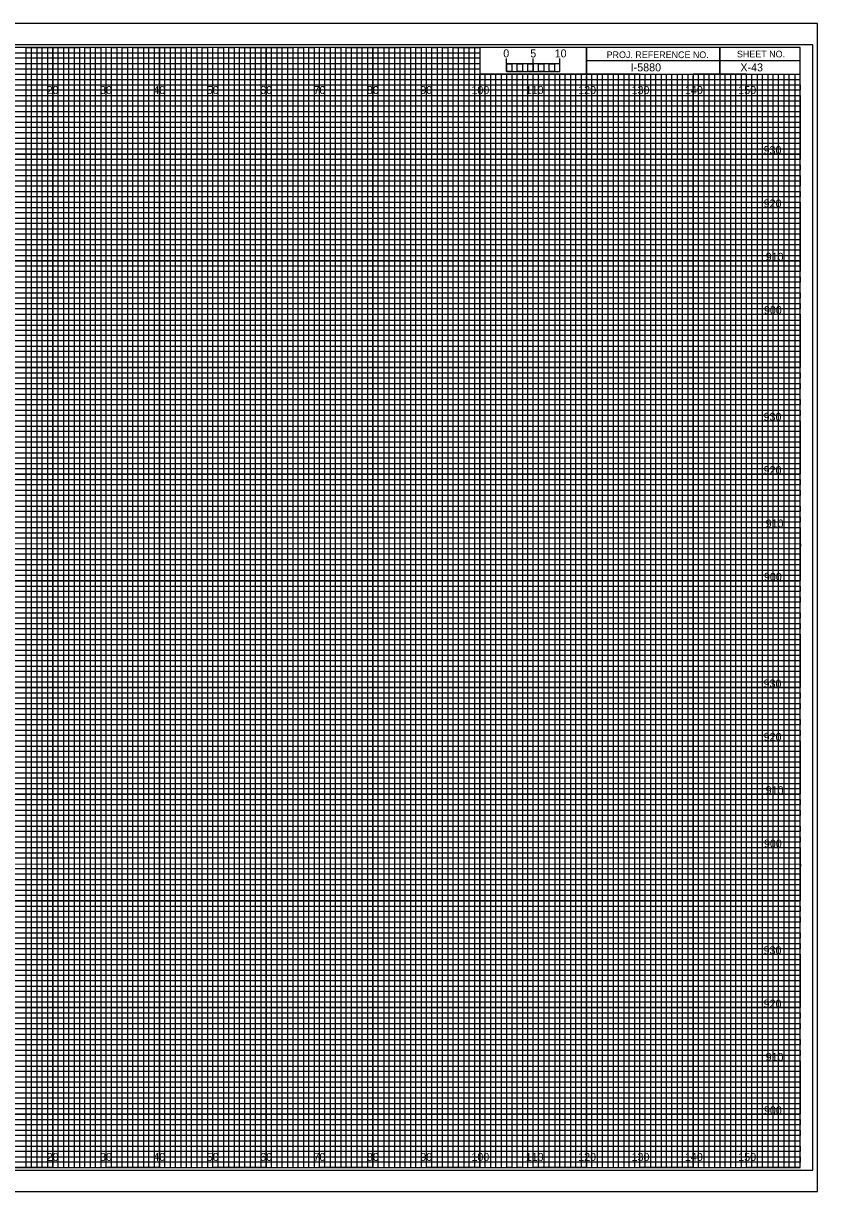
# Model space of a CAD drawing. Extents: x -13 to 323, y -4 to 214.
# Drawn here: x 174.5 to 323.3, y -4.5 to 214.5 of the extents above; entities that cross this region are included whole.
import ezdxf

# ---------------------------------------------------------------- set-up
doc = ezdxf.new("R2010")
doc.units = 0
for name, color, linetype in [('Prop XS Bar Scale Labels', 7, 'Continuous'), ('Prop XS Elevation Labels', 7, 'Continuous'), ('Prop XS Offset Labels', 7, 'Continuous'), ('Prop XS Project Number', 7, 'Continuous'), ('Prop XS Sheet Number', 7, 'Continuous'), ('Sheet Cross Section CELL', 7, 'Continuous'), ('Sheet Cross Section Grid Major CELL', 7, 'Continuous'), ('Sheet Cross Section Grid Middle CELL', 7, 'Continuous'), ('Sheet Cross Section Grid Minor 1 CELL', 7, 'Continuous'), ('Sheet Cross Section Grid Minor 2 CELL', 7, 'Continuous'), ('Sheet Cross Section Scale CELL', 7, 'Continuous'), ('Sheet Cutting Line CELL', 7, 'Continuous'), ('Sheet DOT Grid CELL', 7, 'Continuous'), ('Sheet Plot Border Inside CELL', 7, 'Continuous'), ('Sheet Plot Border Outside CELL', 7, 'Continuous')]:
    doc.layers.add(name, color=color, linetype=linetype)

msp = doc.modelspace()

# ---------------------------------------------------------------- linework, layer by layer
at = {"layer": 'Sheet Cross Section CELL'}
for p, q in [((305, 210), (305, 205)), ((305, 205), (305, 210)), ((280, 207.5), (280, 205)), ((320, 207.49), (280, 207.49)), ((280, 205), (320, 205))]:
    msp.add_line(p, q, dxfattribs=at)
for points in [[(320, 210), (0, 210), (0, 0), (320, 0)], [(280, 210), (260, 210), (260, 205.03), (280, 205.03)], [(320, 210), (280, 210), (280, 205), (320, 205)]]:
    msp.add_lwpolyline(points, close=True, dxfattribs=at)
at = {"layer": 'Sheet Cross Section Grid Major CELL'}
for p, q in [((190, 210), (180, 210)), ((180, 210), (180, 0)), ((190, 0), (190, 210)), ((210, 210), (200, 210)), ((200, 210), (200, 0)), ((210, 0), (210, 210)), ((230, 210), (220, 210)), ((220, 210), (220, 0)), ((230, 0), (230, 210)), ((250, 210), (240, 210)), ((240, 210), (240, 0)), ((250, 0), (250, 210)), ((260, 210), (260, 0)), ((270, 0), (270, 205)), ((290, 205), (280, 205)), ((280, 205), (280, 0)), ((290, 0), (290, 205)), ((310, 205), (300, 205)), ((300, 205), (300, 0)), ((310, 0), (310, 205)), ((180, 0), (170, 0)), ((200, 0), (190, 0)), ((220, 0), (210, 0)), ((240, 0), (230, 0)), ((260, 0), (250, 0)), ((280, 0), (270, 0)), ((300, 0), (290, 0)), ((320, 0), (310, 0)), ((320, 0), (320, 0))]:
    msp.add_line(p, q, dxfattribs=at)
for points in [[(0, 200), (320, 200), (320, 190), (0, 190)], [(0, 180), (320, 180), (320, 170), (0, 170)], [(0, 160), (320, 160), (320, 150), (0, 150)], [(0, 140), (320, 140), (320, 130), (0, 130)], [(0, 120), (320, 120), (320, 110), (0, 110)], [(0, 100), (320, 100), (320, 90), (0, 90)], [(0, 80), (320, 80), (320, 70), (0, 70)], [(0, 60), (320, 60), (320, 50), (0, 50)], [(0, 40), (320, 40), (320, 30), (0, 30)], [(0, 20), (320, 20), (320, 10), (0, 10)]]:
    msp.add_lwpolyline(points, dxfattribs=at)
at = {"layer": 'Sheet Cross Section Grid Middle CELL'}
for points in [[(165, 0), (175, 0), (175, 210), (185, 210), (185, 0), (195, 0), (195, 210), (205, 210), (205, 0), (215, 0), (215, 210), (225, 210), (225, 0), (235, 0), (235, 210), (245, 210), (245, 0), (255, 0), (255, 210), (259.93, 210), (260, 210), (260, 205), (264.99, 205), (264.99, 0), (275, 0), (275, 205), (285, 205), (285, 0), (295, 0), (295, 205), (305, 205), (305, 0), (315, 0), (315, 205)], [(0, 205), (275, 205)], [(0, 185), (320, 185), (320, 195), (0, 195)], [(0, 165), (320, 165), (320, 175), (0, 175)], [(0, 145), (320, 145), (320, 155), (0, 155)], [(0, 125), (320, 125), (320, 135), (0, 135)], [(0, 105), (320, 105), (320, 115), (0, 115)], [(0, 85), (320, 85), (320, 95), (0, 95)], [(0, 65), (320, 65), (320, 75), (0, 75)], [(0, 45), (320, 45), (320, 55), (0, 55)], [(0, 25), (320, 25), (320, 35), (0, 35)], [(0, 5), (320, 5), (320, 15), (0, 15)]]:
    msp.add_lwpolyline(points, dxfattribs=at)
at = {"layer": 'Sheet Cross Section Grid Minor 1 CELL'}
for p, q in [((0, 209), (260, 209)), ((260, 209), (260, 207.98)), ((260, 207.98), (0, 207.98)), ((0, 207), (260, 207)), ((260, 205.89), (0, 205.89)), ((260, 207), (260, 205.89)), ((0, 204), (320, 204))]:
    msp.add_line(p, q, dxfattribs=at)
for points in [[(0, 203), (270, 203), (320, 203), (320, 202), (0, 202)], [(0, 201), (320, 201), (320, 199), (0, 199)], [(0, 198), (320, 198), (320, 197), (0, 196.98)], [(0, 196), (320, 196), (320, 194), (0, 194)], [(0, 193), (320, 193), (320, 192), (0, 192)], [(0, 191), (320, 191), (320, 189), (0, 189)], [(0, 188), (320, 188), (320, 187), (0, 187)], [(0, 186), (320, 186), (320, 184), (0, 184)], [(0, 183), (320, 183), (320, 182), (0, 182)], [(0, 181), (320, 181), (320, 179), (0, 179)], [(0, 178), (320, 178), (320, 177), (0, 177)], [(0, 176), (320, 176), (320, 173.95), (320, 173), (320, 172), (0, 172)], [(0, 174), (320, 174), (320, 173), (0, 173)], [(0, 171), (320, 171), (320, 169), (0, 169.03)], [(0, 169.03), (320, 169), (320, 168), (0, 168)], [(0, 167), (320, 167), (320, 166), (0, 166)], [(0, 164), (320, 164), (320, 163), (0, 163)], [(0, 162), (320, 162), (320, 161), (0, 161)], [(-0.07, 158.89), (320, 158.89), (320, 157.88), (-0.07, 157.88)], [(0, 157), (320, 157), (320, 156), (0, 156)], [(0, 154), (320, 154), (320, 153), (0, 153)], [(0, 152), (320, 152), (320, 151), (0, 151)], [(0, 149), (320, 149), (320, 148), (0, 148)], [(0, 147), (320, 147), (320, 146), (0, 146)], [(0, 144), (320, 144), (320, 143), (0, 143)], [(0, 142), (320, 142), (320, 141), (0, 141)], [(0, 139), (320, 139), (319.99, 137.98), (0, 138)], [(0, 137), (320, 137), (320, 136), (0, 136)], [(0, 134), (320, 134), (320, 133), (0, 133)], [(0, 132), (320, 132), (320, 131), (0, 131)], [(0, 129), (320, 129), (320, 128), (0, 128)], [(0, 127), (320, 127), (320, 126), (0, 126)], [(0, 124), (320, 124), (320, 123), (0, 123)], [(0, 122), (320, 122), (320, 121), (0, 121)], [(0, 119), (320, 119), (320, 118), (0, 118)], [(0, 116.99), (320.07, 116.91), (320, 116), (0, 116)], [(0, 114), (320, 114), (320, 113), (0, 113)], [(0, 112), (320, 112), (320, 111), (0, 111)], [(0, 109), (320, 109), (320, 108), (0, 108)], [(0, 107), (320, 107), (320, 106), (0, 106)], [(0, 104), (320, 104), (320, 103), (0, 103)], [(0, 102), (320, 102), (320, 101), (0, 101)], [(0, 99), (320, 99), (320, 98), (0, 98)], [(0, 97), (320, 97), (320, 96), (0, 96)], [(0, 94), (320, 94), (320, 93), (0, 93)], [(0, 92), (320, 92), (320, 91), (0, 91)], [(0, 89), (320, 89), (320, 88), (0, 88)], [(0, 87), (320, 87), (320, 86), (0, 86)], [(0, 84), (320, 84), (320, 83), (0, 83)], [(0, 82), (320, 82), (320, 81), (0, 81)], [(0, 79), (320, 79), (319.99, 77.98), (0, 78)], [(0, 77), (320, 77), (320, 76), (0, 76)], [(0, 74), (320, 74), (320, 73), (0, 73)], [(0, 72), (320, 72), (320, 71), (0, 71)], [(0, 69), (320, 69), (320, 68), (0, 68)], [(0, 67), (320, 67), (320, 66), (0, 66)], [(0, 64), (320, 64), (320, 63), (0, 63)], [(0, 62), (320, 62), (320, 61), (0, 61)], [(0, 59), (320, 59), (320, 58), (0, 58)], [(0, 56.99), (320.07, 56.91), (320, 56), (0, 56)], [(0, 54), (320, 54), (320, 53), (0, 53)], [(0, 52), (320, 52), (320, 51), (0, 51)], [(0, 49), (320, 49), (320, 48), (0, 48)], [(0, 47), (320, 47), (320, 46), (0, 46)], [(0, 44), (320, 44), (320, 43), (0, 43)], [(0, 42), (320, 42), (320, 41), (0, 41)], [(0, 39), (320, 39), (320, 38), (0, 38)], [(0, 37), (320, 37), (320, 36), (0, 36)], [(0, 34), (320, 34), (320, 33), (0, 33)], [(0, 32), (320, 32), (320, 31), (0, 31)], [(0, 29), (320, 29), (320, 28), (0, 28)], [(0, 27), (320, 27), (320, 26), (0, 26)], [(0, 24), (320, 24), (320, 23), (0, 23)], [(0, 22), (320, 22), (320, 21), (0, 21)], [(0, 19), (320, 19), (320, 18), (0, 18)], [(0, 17), (320, 17), (320, 16), (0, 16)], [(0, 14), (320, 14), (320, 13), (0, 13)], [(0, 12), (320, 12), (320, 11), (0, 11)], [(0, 9), (320, 9), (320, 8), (0, 8)], [(0, 7), (320, 7), (320, 6), (0, 6)], [(0, 4), (320, 4), (320, 3), (0, 3)], [(0, 2), (320, 2), (320, 1), (0, 1)]]:
    msp.add_lwpolyline(points, dxfattribs=at)
at = {"layer": 'Sheet Cross Section Grid Minor 2 CELL'}
for p, q in [((267, 205), (266.01, 205)), ((266.01, 205), (266.01, 0)), ((267, 0), (267, 205)), ((269, 205), (268, 205)), ((268, 205), (268, 0)), ((269, 0), (269, 205)), ((266.01, 0), (265, 0)), ((268, 0), (267, 0))]:
    msp.add_line(p, q, dxfattribs=at)
for points in [[(175, 0), (176, 0), (176, 210), (177, 210), (177, 0)], [(177, 0), (178, 0), (178, 210), (179, 210), (179, 0)], [(180, 0), (181, 0), (181, 210), (182, 210), (182, 0)], [(182, 0), (183, 0), (183, 210), (184, 210), (184, 0)], [(185, 0), (186, 0), (186, 210), (187, 210), (187, 0)], [(187, 0), (188, 0), (188, 210), (189, 210), (189, 0)], [(190, 0), (191, 0), (191, 210), (192, 210), (192, 0)], [(192, 0), (193, 0), (193, 210), (194, 210), (194, 0)], [(195, 0), (196, 0), (196, 210), (197, 210), (197, 0)], [(197, 0), (198, 0), (198, 210), (199, 210), (199, 0)], [(200, 0), (201, 0), (201, 210), (202, 210), (202, 0)], [(202, 0), (203, 0), (203, 210), (204, 210), (204, 0)], [(205, 0), (206, 0), (206, 210), (207, 210), (207, 0)], [(207, 0), (208, 0), (208, 210), (209, 210), (209, 0)], [(210, 0), (211, 0), (211, 210), (212, 210), (212, 0)], [(212, 0), (213, 0), (213, 210), (214, 210), (214, 0)], [(215, 0), (216, 0), (216, 210), (217, 210), (217, 0)], [(217, 0), (218, 0), (218, 210), (219, 210), (219, 0)], [(220, 0), (221, 0), (221, 210), (222, 210), (222, 0)], [(222, 0), (223, 0), (223, 210), (224, 210), (224, 0)], [(225, 0), (226, 0), (226, 210), (227, 210), (227, 0)], [(227, 0), (228, 0), (228, 210), (229, 210), (229, 0)], [(230, 0), (231, 0), (231, 210), (232, 210), (232, 0)], [(232, 0), (233, 0), (233, 210), (234, 210), (234, 0)], [(235, 0), (236, 0), (236, 210), (237, 210), (237, 0)], [(237, 0), (238, 0), (238, 210), (239, 210), (239, 0)], [(240, 0), (241, 0), (241, 210), (242, 210), (242, 0)], [(242, 0), (243, 0), (243, 210), (244, 210), (244, 0)], [(245, 0), (246, 0), (246, 210), (247, 210), (247, 0)], [(247, 0), (248, 0), (248, 210), (249, 210), (249, 0)], [(250, 0), (251, 0), (251, 210), (252, 210), (252, 0)], [(252, 0), (253, 0), (253, 210), (254, 210), (254, 0)], [(255, 0), (256, 0), (256, 210), (257, 210), (257, 0)], [(257, 0), (258, 0), (258, 210), (259, 210), (259, 0)], [(260, 0), (261, 0), (261, 205), (262.02, 205), (262.02, 0)], [(262, 0), (263, 0), (263, 205), (263.99, 205), (263.99, 0)], [(270, 0), (270.98, 0), (270.98, 205), (272, 205), (272, 0)], [(272, 0), (273, 0), (273, 205), (274.05, 205), (274.05, 0)], [(275, 0), (276, 0), (276, 205), (277, 205), (277, 0)], [(277, 0), (278, 0), (278, 205), (279, 205), (279, 0)], [(280, 0), (281, 0), (281, 205), (282, 205), (282, 0)], [(282, 0), (283, 0), (283, 205), (284, 205), (284, 0)], [(285, 0), (286, 0), (286, 205), (287, 205), (287, 0)], [(287, 0), (288, 0), (288, 205), (289, 205), (289, 0)], [(290, 0), (291, 0), (291, 205), (292, 205), (292, 0)], [(292, 0), (293, 0), (293, 205), (294, 205), (294, 0)], [(295, 0), (296, 0), (296, 205), (297, 205), (297, 0)], [(297, 0), (298, 0), (298, 205), (299, 205), (299, 0)], [(300, 0), (301, 0), (301, 205), (302, 205), (302, 0)], [(302, 0), (303, 0), (303, 205), (304, 205), (304, 0)], [(305, 0), (306, 0), (306, 205), (307, 205), (307, 0)], [(307, 0), (308, 0), (308, 205), (309, 205), (309, 0)], [(310, 0), (311, 0), (311, 205), (312, 205), (312, 0)], [(312, 0), (313, 0), (313, 205), (314, 205), (314, 0)], [(315, 0), (316, 0), (316, 205), (317, 205), (317, 0)], [(317, 0), (318, 0), (318, 205), (319, 205), (319, 0)]]:
    msp.add_lwpolyline(points, dxfattribs=at)
at = {"layer": 'Sheet Cross Section Scale CELL'}
for p, q in [((265, 205.49), (265, 207.9)), ((265, 206.9), (265, 207.9)), ((270, 205.49), (270, 207.9)), ((275, 205.49), (275, 207.9)), ((275, 206.9), (275, 207.9))]:
    msp.add_line(p, q, dxfattribs=at)
for points in [[(275, 206.9), (265, 206.9), (265, 205.49), (275, 205.49)], [(265, 206.9), (266, 206.9), (266, 205.49), (265, 205.49)], [(267, 206.9), (268, 206.9), (268, 205.49), (267, 205.49)], [(269, 206.9), (270, 206.9), (270, 205.49), (269, 205.49)], [(271, 206.9), (272, 206.9), (272, 205.49), (271, 205.49)], [(273, 206.9), (274, 206.9), (274, 205.49), (273, 205.49)]]:
    msp.add_lwpolyline(points, close=True, dxfattribs=at)
at = {"layer": 'Sheet Cutting Line CELL'}
for p, q in [((323.3, 214.5), (-13.4, 214.5)), ((-13.4, -4.5), (323.3, -4.5))]:
    msp.add_line(p, q, dxfattribs=at)
at = {"layer": 'Sheet DOT Grid CELL'}
for p, q in [((180, 0), (180, 210)), ((190, 0), (190, 210)), ((200, 0), (200, 210)), ((210, 0), (210, 210)), ((220, 0), (220, 210)), ((230, 0), (230, 210)), ((240, 0), (240, 210)), ((250, 0), (250, 210)), ((260, 0), (260, 204.69)), ((270, 0), (270, 204.69)), ((280, 0), (280, 204.69)), ((290, 0), (290, 204.69)), ((300, 0), (300, 204.69)), ((310, 0), (310, 204.69)), ((0, 200), (320, 200)), ((0, 190), (320, 190)), ((0, 180), (320, 180)), ((0, 170), (320, 170)), ((0, 160), (320, 160)), ((0, 150), (320, 150)), ((0, 140), (320, 140)), ((0, 130), (320, 130)), ((0, 120), (320, 120)), ((0, 110), (320, 110)), ((0, 100), (320, 100)), ((0, 90), (320, 90)), ((0, 80), (320, 80)), ((0, 70), (320, 70)), ((0, 60), (320, 60)), ((0, 50), (320, 50)), ((0, 40), (320, 40)), ((0, 30), (320, 30)), ((0, 20), (320, 20)), ((0, 10), (320, 10))]:
    msp.add_line(p, q, dxfattribs=at)
at = {"layer": 'Sheet Plot Border Inside CELL'}
msp.add_lwpolyline([(-10.8, -0.5), (322.4, -0.5), (322.4, 210.5), (-10.8, 210.5)], close=True, dxfattribs=at)
at = {"layer": 'Sheet Plot Border Outside CELL'}
msp.add_lwpolyline([(-13.4, -4.5), (323.3, -4.5), (323.3, 214.5), (-13.4, 214.5)], close=True, dxfattribs=at)

# ---------------------------------------------------------------- texts
at = {"layer": 'Prop XS Bar Scale Labels'}
for s, p in [('5', (269.47, 208.12)), ('10', (274.04, 208.12))]:
    msp.add_text(s, height=1.5, dxfattribs=at).set_placement(p)
at = {"layer": 'Prop XS Elevation Labels'}
for s, p in [('930', (313.18, 190)), ('920', (313.19, 180)), ('910', (313.57, 170)), ('900', (313.24, 160)), ('930', (313.18, 140)), ('920', (313.19, 130)), ('910', (313.57, 120)), ('900', (313.24, 110)), ('930', (313.18, 90)), ('920', (313.19, 80)), ('910', (313.57, 70)), ('900', (313.24, 60)), ('930', (313.18, 40)), ('920', (313.19, 30)), ('910', (313.57, 20)), ('900', (313.24, 10))]:
    msp.add_text(s, height=1.5, dxfattribs=at).set_placement(p)
at = {"layer": 'Prop XS Offset Labels'}
for s, p in [('20', (178.86, 201.25)), ('30', (188.86, 201.25)), ('40', (198.86, 201.25)), ('50', (208.86, 201.25)), ('60', (218.86, 201.25)), ('70', (228.86, 201.25)), ('80', (238.86, 201.25)), ('90', (248.86, 201.25)), ('100', (258.44, 201.25)), ('110', (268.62, 201.25)), ('120', (278.44, 201.25)), ('130', (288.44, 201.25)), ('140', (298.44, 201.25)), ('150', (308.44, 201.25)), ('20', (178.86, 1.25)), ('30', (188.86, 1.25)), ('40', (198.86, 1.25)), ('50', (208.86, 1.25)), ('60', (218.86, 1.25)), ('70', (228.86, 1.25)), ('80', (238.86, 1.25)), ('90', (248.86, 1.25)), ('100', (258.44, 1.25)), ('110', (268.62, 1.25)), ('120', (278.44, 1.25)), ('130', (288.44, 1.25)), ('140', (298.44, 1.25)), ('150', (308.44, 1.25))]:
    msp.add_text(s, height=1.5, dxfattribs=at).set_placement(p)
at = {"layer": 'Prop XS Project Number'}
msp.add_text('I-5880', height=1.5, dxfattribs=at).set_placement((288.28, 205.5))
at = {"layer": 'Prop XS Sheet Number'}
msp.add_text('X-43', height=1.5, dxfattribs=at).set_placement((308.83, 205.5))
at = {"layer": 'Sheet Cross Section CELL'}
for s, p in [('PROJ. REFERENCE NO.', (283.77, 207.99)), ('SHEET NO.', (308.19, 208.12))]:
    msp.add_text(s, height=1.25, dxfattribs=at).set_placement(p)
at = {"layer": 'Sheet Cross Section Scale CELL'}
msp.add_text('0', height=1.5, dxfattribs=at).set_placement((264.41, 208.12))

doc.saveas('drawing.dxf')
